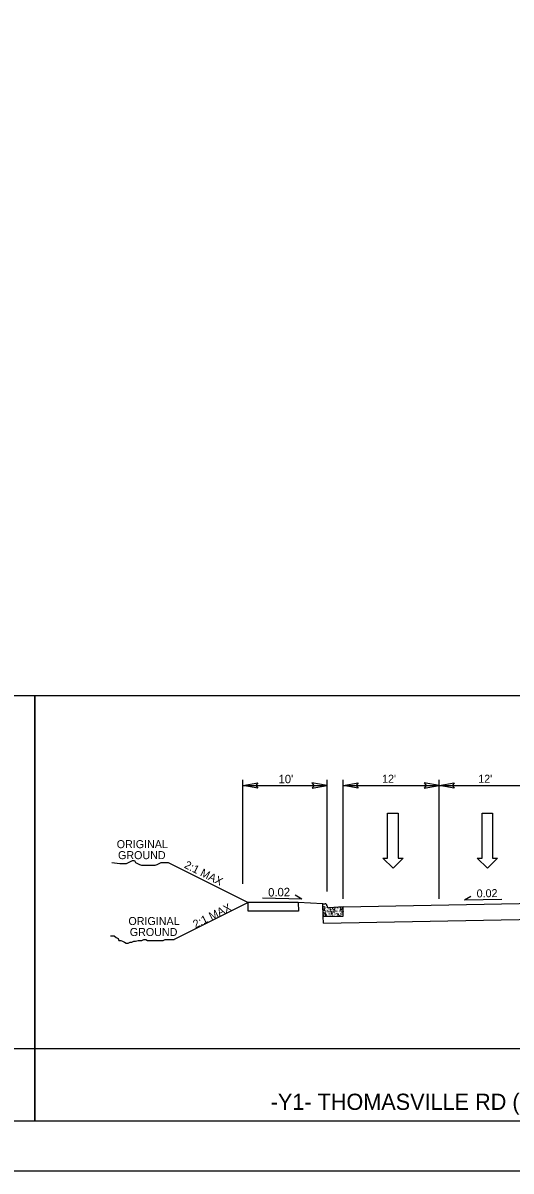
# Model space of a CAD drawing. Extents: x 1636954 to 1644154, y 841334 to 845582.
# Drawn here: x 1639588 to 1640076, y 841334 to 842484 of the extents above; entities that cross this region are included whole.
import ezdxf

# ---------------------------------------------------------------- set-up
doc = ezdxf.new("R2010")
doc.units = 0
for name, color, linetype in [('Prop Dimension', 7, 'Continuous'), ('Prop Lane Lines', 7, 'Continuous'), ('Prop PHM Legend CELL', 7, 'Continuous'), ('Scratch_Level_1', 7, 'Continuous'), ('Sheet Plan And Profile CELL', 7, 'Continuous'), ('Typical Curb CELL', 7, 'Continuous'), ('Typical Hinge Slope Arterial CELL', 7, 'Continuous'), ('Typical Hinge Slope Interstate CELL', 7, 'Continuous'), ('Typical Pavement Slope CELL', 7, 'Continuous'), ('Typical Pavement Slope Information CELL', 7, 'Continuous'), ('Typical Shoulder Slope CELL', 7, 'Continuous'), ('Typical Text General CELL', 7, 'Continuous')]:
    doc.layers.add(name, color=color, linetype=linetype)

msp = doc.modelspace()

# ---------------------------------------------------------------- linework, layer by layer
at = {"layer": 'Prop Dimension'}
for p, q in [((1639807.7, 841621.7), (1639807.7, 841725.6)), ((1639807.7, 841720), (1639892.1, 841720)), ((1639892.1, 841614), (1639892.1, 841725.6)), ((1639908.1, 841606.4), (1639908.1, 841725.6)), ((1639908.1, 841720), (1640004.4, 841720)), ((1640004.4, 841606.4), (1640004.4, 841725.6)), ((1640004.4, 841720), (1640100.6, 841720)), ((1639952.8, 841647.4), (1639952.8, 841692.3)), ((1639952.8, 841692.3), (1639963.4, 841692.3)), ((1639963.4, 841692.3), (1639963.4, 841647.4)), ((1640047.3, 841647.4), (1640047.3, 841692.3)), ((1640047.3, 841692.3), (1640057.9, 841692.3)), ((1640057.9, 841692.3), (1640057.9, 841647.4)), ((1639958.2, 841637.3), (1639948, 841647.4)), ((1639948, 841647.4), (1639952.8, 841647.4)), ((1639968.2, 841647.4), (1639958.2, 841637.3)), ((1639963.4, 841647.4), (1639968.2, 841647.4)), ((1640052.8, 841637.3), (1640042.5, 841647.4)), ((1640042.5, 841647.4), (1640047.3, 841647.4)), ((1640062.7, 841647.4), (1640052.8, 841637.3)), ((1640057.9, 841647.4), (1640062.7, 841647.4))]:
    msp.add_line(p, q, dxfattribs=at)
for points in [[(1639822.8, 841717.4), (1639807.7, 841720), (1639822.8, 841722.7), (1639820.9, 841720)], [(1639877.1, 841717.4), (1639892.1, 841720), (1639877, 841722.7), (1639878.9, 841720)], [(1639923.1, 841717.4), (1639908.1, 841720), (1639923.2, 841722.7), (1639921.3, 841720)], [(1639989.3, 841717.4), (1640004.4, 841720), (1639989.3, 841722.7), (1639991.2, 841720)], [(1640019.4, 841717.4), (1640004.4, 841720), (1640019.5, 841722.7), (1640017.6, 841720)]]:
    msp.add_lwpolyline(points, close=True, dxfattribs=at)
at = {"layer": 'Prop PHM Legend CELL'}
msp.add_line((1637654.2, 841456.6), (1640851.7, 841456.6), dxfattribs=at)
for points in [[(1637654.2, 841810.2), (1639599.4, 841810.2), (1639599.4, 841383.9), (1637654.2, 841383.9)], [(1639599.4, 841810.2), (1640851.7, 841810.2), (1640851.7, 841383.9), (1639599.4, 841383.9)]]:
    msp.add_lwpolyline(points, close=True, dxfattribs=at)
at = {"layer": 'Scratch_Level_1'}
msp.add_lwpolyline([(1636954.2, 841333.9), (1636954.2, 844733.9), (1644154.2, 844733.9), (1644154.2, 841333.9)], close=True, dxfattribs=at)
at = {"layer": 'Sheet Plan And Profile CELL'}
msp.add_lwpolyline([(1637004.2, 841383.9), (1637004.2, 844683.9), (1644104.2, 844683.9), (1644104.2, 841383.9)], close=True, dxfattribs=at)
at = {"layer": 'Typical Curb CELL'}
for p, q in [((1639888, 841601.5), (1639890.1, 841601.6)), ((1639888.2, 841588.7), (1639888, 841601.5)), ((1639888.4, 841598.5), (1639889.6, 841598.9)), ((1639889.5, 841598.1), (1639888.4, 841598.5)), ((1639889.4, 841596), (1639888.6, 841595.3)), ((1639888.6, 841595.3), (1639889.9, 841595)), ((1639889.9, 841595), (1639889.4, 841596)), ((1639889.6, 841598.9), (1639889.5, 841598.1)), ((1639892.1, 841599.6), (1639892.1, 841599.7)), ((1639908.1, 841598.5), (1639894.1, 841597.7)), ((1639895.4, 841596.5), (1639895.1, 841595.6)), ((1639895.1, 841595.6), (1639896.1, 841595.5)), ((1639896.1, 841595.5), (1639895.4, 841596.5)), ((1639899.4, 841596.1), (1639898.6, 841595.5)), ((1639898.6, 841595.5), (1639899.9, 841595.2)), ((1639899.9, 841595.2), (1639899.4, 841596.1)), ((1639905.4, 841596.7), (1639905.1, 841595.7)), ((1639905.1, 841595.7), (1639906.1, 841595.7)), ((1639906.1, 841595.7), (1639905.4, 841596.7)), ((1639908.3, 841589.1), (1639908.1, 841598.5)), ((1639888.2, 841588.7), (1639908.3, 841589.1)), ((1639890.5, 841592.4), (1639889.7, 841591.7)), ((1639889.7, 841591.7), (1639891, 841591.4)), ((1639891, 841591.4), (1639890.5, 841592.4)), ((1639896.9, 841592.8), (1639896.1, 841592.2)), ((1639896.1, 841592.2), (1639897.5, 841591.9)), ((1639897.5, 841591.9), (1639896.9, 841592.8)), ((1639903.4, 841591.5), (1639902.6, 841590.8)), ((1639902.6, 841590.8), (1639903.9, 841590.5)), ((1639903.9, 841590.5), (1639903.4, 841591.5))]:
    msp.add_line(p, q, dxfattribs=at)
for centre in [(1639888.1, 841600.6), (1639888.6, 841599.2), (1639889.3, 841593.9), (1639889.4, 841597), (1639889.9, 841600.9), (1639890.3, 841597.4), (1639890.7, 841594.2), (1639891.8, 841596.1), (1639892.1, 841593.8), (1639892.4, 841597.7), (1639892.5, 841597.3), (1639892.5, 841594.7), (1639892.8, 841595.9), (1639893.5, 841594), (1639894, 841596.6), (1639894.2, 841597.4), (1639895.1, 841594.2), (1639895.5, 841593.1), (1639895.8, 841597.1), (1639896.4, 841593.7), (1639896.5, 841597.6), (1639896.8, 841595.6), (1639897.4, 841596.9), (1639897.6, 841595.2), (1639897.8, 841597.1), (1639898, 841596.4), (1639898.1, 841593.9), (1639899.4, 841597.2), (1639899.3, 841594), (1639899.3, 841593), (1639900.4, 841597.6), (1639900.7, 841594.4), (1639901.8, 841596.3), (1639902.1, 841593.9), (1639902.4, 841597.8), (1639902.6, 841597.4), (1639902.6, 841594.8), (1639902.8, 841596.1), (1639903.5, 841594.2), (1639904, 841596.8), (1639904.2, 841597.6), (1639905.1, 841594.4), (1639905.4, 841598.1), (1639905.8, 841597.3), (1639906.4, 841593.8), (1639906.5, 841598), (1639906.8, 841595.7), (1639907.3, 841593), (1639907.4, 841597), (1639907.6, 841595.4), (1639907.9, 841597.3), (1639908, 841596.5), (1639908.1, 841594), (1639888.6, 841591.5), (1639889.1, 841592.6), (1639889.1, 841590.1), (1639890.4, 841590.3), (1639890.7, 841589.4), (1639891.7, 841590.6), (1639892.1, 841589.6), (1639892.9, 841592.5), (1639893.2, 841590.1), (1639893.6, 841591.1), (1639893.9, 841592.3), (1639894.5, 841590.4), (1639895.1, 841591.9), (1639895.6, 841590.6), (1639896, 841589.6), (1639896.8, 841590.7), (1639897.4, 841589.9), (1639898.2, 841591.1), (1639899.1, 841589.6), (1639899.6, 841590.6), (1639900.1, 841591.5), (1639900.3, 841592.8), (1639900.5, 841589.9), (1639901, 841590.8), (1639901.5, 841590.5), (1639902, 841591.7), (1639902.1, 841589.2), (1639903.2, 841592.2), (1639903.3, 841589.4), (1639904.6, 841592.5), (1639904.7, 841589.7), (1639905.8, 841591.6), (1639905.9, 841592.8), (1639906.1, 841589.2), (1639906.5, 841590.2), (1639906.8, 841591.4), (1639907.5, 841589.5)]:
    msp.add_circle(centre, 0.0643, dxfattribs=at)
for centre, start, end in [((1639890.1, 841599.6), 0.8814, 90.8814), ((1639894, 841599.6), 180.8814, 273.2659)]:
    msp.add_arc(centre, 1.92, start, end, dxfattribs=at)
at = {"layer": 'Typical Hinge Slope Arterial CELL'}
msp.add_lwpolyline([(1639676.6, 841643), (1639684.5, 841642), (1639686.5, 841642), (1639689.5, 841642), (1639691.4, 841642), (1639693.4, 841643), (1639695.4, 841644), (1639697.4, 841645), (1639699.3, 841645), (1639700.3, 841643), (1639702.3, 841642), (1639704.3, 841641.1), (1639706.2, 841640.1), (1639708.2, 841640.1), (1639710.2, 841640.1), (1639712.2, 841640.1), (1639714.1, 841640.1), (1639716.1, 841640.1), (1639718.1, 841640.1), (1639720.1, 841640.1), (1639722, 841641.1), (1639724, 841642), (1639726, 841643), (1639729, 841643), (1639730.9, 841643), (1639732.9, 841643)], dxfattribs=at)
at = {"layer": 'Typical Hinge Slope Interstate CELL'}
for p, q in [((1639732.9, 841643), (1639813.1, 841603)), ((1639813.1, 841603), (1639739.1, 841565.9))]:
    msp.add_line(p, q, dxfattribs=at)
msp.add_lwpolyline([(1639675.4, 841569.6), (1639677.2, 841569.6), (1639679.1, 841569.6), (1639680.9, 841567.7), (1639682.8, 841566.8), (1639683.7, 841564.9), (1639685.5, 841564.9), (1639687.4, 841564), (1639689.2, 841563.1), (1639691.1, 841562.2), (1639692.9, 841562.2), (1639694.8, 841563.1), (1639696.6, 841563.1), (1639698.5, 841564), (1639700.3, 841564), (1639703.1, 841564.9), (1639704.9, 841564.9), (1639706.8, 841564.9), (1639708.6, 841565.9), (1639710.5, 841565.9), (1639712.3, 841564.9), (1639714.2, 841564.9), (1639716, 841564.9), (1639717.9, 841564.9), (1639719.7, 841564.9), (1639722.5, 841564.9), (1639725.3, 841564.9), (1639728, 841564.9), (1639729.9, 841565.9), (1639732.7, 841565.9), (1639735.4, 841565.9), (1639739.1, 841565.9)], dxfattribs=at)
at = {"layer": 'Typical Pavement Slope CELL'}
for p, q in [((1639908.1, 841598.5), (1640116, 841602.6)), ((1639888.4, 841582.1), (1639888.2, 841588.7)), ((1639888.4, 841582.1), (1640116, 841586.6))]:
    msp.add_line(p, q, dxfattribs=at)
at = {"layer": 'Typical Pavement Slope Information CELL'}
for p, q in [((1639866.7, 841606.3), (1639827.4, 841607.1)), ((1639866.7, 841606.3), (1639860.1, 841610.3)), ((1640029.8, 841605.4), (1640036.1, 841609.2)), ((1640029.8, 841605.4), (1640067.2, 841606.1))]:
    msp.add_line(p, q, dxfattribs=at)
at = {"layer": 'Typical Shoulder Slope CELL'}
for p, q in [((1639863.2, 841603), (1639813.1, 841603)), ((1639813.1, 841594.2), (1639813.1, 841603)), ((1639863.4, 841594.2), (1639813.1, 841594.2)), ((1639888, 841601.5), (1639863.2, 841603)), ((1639863.2, 841603), (1639863.4, 841594.2))]:
    msp.add_line(p, q, dxfattribs=at)

# ---------------------------------------------------------------- texts
at = {"layer": 'Prop Dimension'}
msp.add_text("10'", height=8.44, rotation=360, dxfattribs=at).set_placement((1639843.5, 841722.3))
at = {"layer": 'Prop Lane Lines'}
for s, p in [('ORIGINAL', (1639681.5, 841657.3)), ('GROUND', (1639682.8, 841646.3)), ('ORIGINAL', (1639693.2, 841580.3)), ('GROUND', (1639694.6, 841569.3))]:
    msp.add_text(s, height=8.02, dxfattribs=at).set_placement(p)
at = {"layer": 'Typical Hinge Slope Interstate CELL'}
for rotation, p in [(333.4354, (1639748.4, 841638)), (26.5646, (1639760.3, 841576.9))]:
    msp.add_text('2:1 MAX', height=8.02, rotation=rotation, dxfattribs=at).set_placement(p)
at = {"layer": 'Typical Pavement Slope Information CELL'}
for p in [(1639947.2, 841722.8), (1640043.5, 841722.8)]:
    msp.add_text("12'", height=8.02, dxfattribs=at).set_placement(p)
for height, p in [(8.44, (1639833.2, 841608.8)), (8.02, (1640042, 841607.9))]:
    msp.add_text('0.02', height=height, rotation=1.1457, dxfattribs=at).set_placement(p)
at = {"layer": 'Typical Text General CELL'}
msp.add_text('-Y1- THOMASVILLE RD (I-40 INTERCHANGE SOUTH TO CHARLES ST)', height=16.2, dxfattribs=at).set_placement((1639835.7, 841395.2))

doc.saveas('drawing.dxf')
